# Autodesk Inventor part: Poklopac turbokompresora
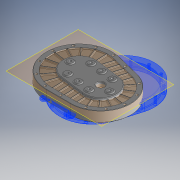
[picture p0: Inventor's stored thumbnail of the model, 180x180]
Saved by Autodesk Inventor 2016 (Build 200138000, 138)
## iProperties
Created: 2015-08
Part Number: Poklopac turbokompresora
Material: Generic
Document SubType Name: Modeling
Designer: stank
Density: 1 g/cm^3
Appearance: Default
Mass: 800.115 g
Surface Area: 1829.7 cm^2
Volume: 800.115 cm^3
Author: stank
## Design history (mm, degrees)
workplane "Work Plane3"
sketch "Sketch3"
  geometry: L1 (25.713, -105.228)-(-56.137, -104.923); L2 (26.085, -5.229)-(-52.114, 11.649); L3 (26.085, -5.229)-(-55.727, 5.076); L4 (25.769, -90.228)-(-56.081, -89.923); L5 (-32.512, 97.196)-(46.857, 77.194); L6 (50.522, 91.74)-(-28.846, 111.741); C1 r 9 at (26.085, -5.229) reference; C2 r 4.5 at (43.468, -93.366) reference; C3 r 4.5 at (-58.597, -126.199) reference; C4 r 4.5 at (-148.255, -75.856) reference; C5 r 4.5 at (-134.233, 101.873) reference; C6 r 4.5 at (-46.759, 125.523) reference; C7 r 4.5 at (25.538, 82.325) reference; A1 r 100 centre (26.085, -5.229) between (25.713, -105.228) and (50.522, 91.74); A2 r 110 centre (-55.727, 5.076) between (-28.846, 111.741) and (-56.137, -104.923); A3 r 85 centre (26.085, -5.229) between (25.769, -90.228) and (46.857, 77.194); A4 r 95 centre (-55.727, 5.076) between (-32.512, 97.196) and (-56.081, -89.923); 1 further point
  constraints: 12 end point, 8 point on circle, 6 tangent, 4 centre point, 2 parallel, 2 other
  dimensions: "d7" = 110 radius of A2; "d8" = 100 radius of A1; "d18" = 5 deg angle of L2 L3; "d26" = 15 distance between parallel lines of L1 L4; "d148" = 15 radial gap between concentric circles of A1 A3
extrude "Extrusion1" new body sketch "Sketch3" distance "d13" = 25; taper "d14" = 0 deg
sketch "Sketch7"
  geometry: L1 (50.522, 91.74)-(-28.846, 111.741) reference; L2 (-56.137, -104.923)-(25.713, -105.228) reference; C1 r 4 at (-41.402, 31.566) reference; C2 r 4 at (-38.197, -5.064) reference; C3 r 4 at (-13.762, -8.715) reference; C4 r 4 at (-4.556, 20.483) reference; C5 r 4 at (22.599, 34.619) reference; C6 r 4 at (51.797, 25.413) reference; C7 r 4 at (65.933, -1.742) reference; C8 r 4 at (56.727, -30.94) reference; C9 r 4 at (31.273, -44.891) reference; C10 r 4 at (0.374, -35.87) reference; A1 r 110 centre (-55.727, 5.076) between (-28.846, 111.741) and (-56.137, -104.923) reference; A2 r 100 centre (26.085, -5.229) between (25.713, -105.228) and (50.522, 91.74) reference; 1 further point
extrude "Extrusion3" join sketch "Sketch7" distance "d42" = 10; taper "d43" = 0 deg
sketch "Sketch8"
  geometry: L1 (25.769, -90.228)-(-56.081, -89.923) reference; L2 (-32.512, 97.196)-(46.857, 77.194) reference; C1 r 4 at (65.933, -1.742) reference; C2 r 4 at (56.727, -30.94) reference; C3 r 4 at (31.273, -44.891) reference; C4 r 4 at (0.374, -35.87) reference; C5 r 4 at (-13.762, -8.715) reference; C6 r 4 at (-38.197, -5.064) reference; C7 r 4 at (-4.556, 20.483) reference; C8 r 4 at (22.599, 34.619) reference; C9 r 4 at (51.797, 25.413) reference; C10 r 4 at (-41.402, 31.566) reference; C11 r 10 at (65.933, -1.742); C12 r 10 at (56.727, -30.94); C13 r 4 at (31.273, -44.891) reference; C14 r 10 at (31.273, -44.891); C15 r 10 at (0.374, -35.87); C16 r 4 at (-13.762, -8.715) reference; C17 r 10 at (-13.762, -8.715); C18 r 10 at (-38.197, -5.064); C19 r 10 at (-41.402, 31.566); C20 r 10 at (-4.556, 20.483); C21 r 4 at (22.599, 34.619) reference; C22 r 10 at (22.599, 34.619); C23 r 10 at (51.797, 25.413); A1 r 85 centre (26.085, -5.229) between (25.769, -90.228) and (46.857, 77.194) reference; A2 r 95 centre (-55.727, 5.076) between (-32.512, 97.196) and (-56.081, -89.923) reference; 1 further point
  constraints: 10 centre point, 10 coincident
  dimensions: "d44" = 20 diameter of C11; "d45" = 20 diameter of C12; "d46" = 20 diameter of C14; "d47" = 20 diameter of C15; "d48" = 20 diameter of C17; "d49" = 20 diameter of C20; "d50" = 20 diameter of C22; "d51" = 20 diameter of C23; "d52" = 20 diameter of C18; "d54" = 20 diameter of C19
extrude "Extrusion5" cut sketch "Sketch8" distance "d58" = 5; taper "d59" = 0 deg
sketch "Sketch10"
  geometry: C1 r 10 at (26.085, -5.229) reference; C2 r 11 at (26.085, -5.229); C3 r 16 at (26.085, -5.229); 1 further point
  constraints: 2 centre point, 2 coincident
  dimensions: "d60" = 1 radial gap between concentric circles of C1 C2; "d61" = 5 radial gap between concentric circles of C2 C3
extrude "Extrusion6" join sketch "Sketch10" distance "d62" = 3; taper "d63" = 0 deg
sketch "Sketch11"
  geometry: C1 r 11 at (0, 0) reference; 1 further point
extrude "Extrusion7" cut sketch "Sketch11" stored distance "d64" = 17; taper "d65" = 0 deg
chamfer "Chamfer3" distance "d71" = 1; stored, may be unused: second distance "d72" = 2, angle "d73" = 45 deg
workplane "Work Plane4"
sketch "Sketch12"
  geometry: L1 (26.085, -5.229)-(142.594, 145.734); L2 (26.085, -5.229)-(154.434, 22.85); L3 (26.085, -5.229)-(167.155, -24.202); L4 (26.085, -5.229)-(157.504, 77.979); L5 (101.371, 11.241)-(82.975, 7.217); L6 (89.461, -13.752)-(105.105, -15.856); L7 (75.965, 59.402)-(67.391, 48.291); L8 (92.041, 36.531)-(78.659, 28.059); L9 (-29.09, 110.772)-(50.278, 90.77) reference; L10 (25.717, -104.228)-(-56.133, -103.923) reference; L11 (-25.39, 100.364)-(51.872, 75.766) reference; L12 (30.981, -90.088)-(-49.967, -94.758) reference; L13 (-55.727, 5.076)-(-59.81, 104.993); L14 (-55.727, 5.076)-(-93.737, 97.571); L15 (-55.727, 5.076)-(-123.08, 78.992); L16 (-55.727, 5.076)-(-144.299, 51.499); L17 (-55.727, 5.076)-(-154.834, 18.406); L18 (-55.727, 5.076)-(-153.416, -16.295); L19 (-55.727, 5.076)-(26.085, -5.229); L20 (26.085, -5.229)-(51.872, 75.766); L21 (26.085, -5.229)-(51.872, 75.766); L22 (4.813, -2.549)-(31.782, 82.161); L23 (4.813, -2.549)-(8.443, -91.388); L24 (12.725, 88.229)-(-15.367, -0.007); L25 (-15.367, -0.007)-(-11.586, -92.543); L26 (-31.615, -93.699)-(-35.547, 2.534); L27 (-55.727, 5.076)-(-25.39, 100.364); L28 (-6.333, 94.296)-(-35.547, 2.534); L29 (49.768, 69.156)-(45.412, 55.475); L30 (49.768, 69.156)-(44.535, 52.72); L31 (29.678, 75.552)-(25.322, 61.871); L32 (9.933, 79.461)-(6.511, 68.711); L33 (-8.264, 88.229)-(-12.767, 74.086); L34 (-28.182, 91.595)-(-33.756, 74.086); L35 (-59.441, 95.979)-(-58.836, 81.156); L36 (-90.32, 89.255)-(-83.292, 72.154); L37 (-119.318, 74.864)-(-107.974, 62.414); L38 (-121.726, 39.668)-(-133.857, 46.026); L39 (-122.61, 14.072)-(-138.942, 16.268); L40 (-117.386, -8.413)-(-135.718, -12.423); L41 (-52.925, -63.49)-(-52.216, -80.841); L42 (-32.666, -67.96)-(-32.069, -82.577); L43 (-12.596, -67.814)-(-11.825, -86.696); L44 (7.37, -65.125)-(8.077, -82.428); L45 (26.085, -5.229)-(101.371, -44.688); L46 (26.085, -5.229)-(83.335, -68.057); L47 (26.085, -5.229)-(58.394, -83.849); L48 (26.085, -5.229)-(29.556, -90.158); L49 (-55.727, 5.076)-(-140.216, -48.418); L50 (-55.727, 5.076)-(-116.824, -74.089); L51 (-55.727, 5.076)-(-86.064, -90.211); L52 (-55.727, 5.076)-(-51.644, -94.84); L53 (83.335, -35.235)-(95.897, -41.818); L54 (65.44, -48.418)-(77.011, -61.116); L55 (49.052, -61.116)-(54.383, -74.089); L56 (28.634, -67.603)-(29.2, -81.44); L57 (-78.06, -65.073)-(-82.518, -79.075); L58 (-97.971, -49.661)-(-106.812, -61.116); L59 (-110.873, -29.84)-(-129.792, -41.818); C1 r 11 at (26.085, -5.229); C2 r 11 at (26.085, -5.229) reference; A1 r 100 centre (26.085, -5.229) between (25.713, -105.228) and (50.522, 91.74) reference; A2 r 110 centre (-55.727, 5.076) between (-28.846, 111.741) and (-56.137, -104.923) reference; A3 r 99 centre (26.085, -5.229) between (25.717, -104.228) and (50.278, 90.77) reference; A4 r 109 centre (-55.727, 5.076) between (-29.09, 110.772) and (-56.133, -103.923) reference; A5 r 85 centre (26.085, -5.229) between (30.981, -90.088) and (51.872, 75.766) reference; A6 r 100 centre (-55.727, 5.076) between (-25.39, 100.364) and (-49.967, -94.758) reference; A7 r 85 centre (26.085, -5.229) between (25.769, -90.228) and (46.857, 77.194) reference; A8 r 85 centre (26.085, -5.229) between (25.769, -90.228) and (46.857, 77.194) reference; 3 further points; 3 other entities
  constraints: 110 end point, 54 point on line, 14 point on circle, 6 parallel, 1 centre point, 1 coincident, 1 collinear, 1 perpendicular, 25 other
  dimensions: "d81" = 20 deg angle of L1 L4; "d82" = 20 deg angle of L2 L4; "d83" = 20 deg angle of L2 L3; "d194" = 20 deg angle of L13 L27; "d195" = 20 deg angle of L14 L13; "d196" = 20 deg angle of L14 L15; "d199" = 20 deg angle of L17 L16; "d200" = 20 deg angle of L17 L18; "d206" = 20 deg angle of L20 L1; "d207" = 20 deg angle of L15 L16; "d208" = 20 deg angle of L45 L3; "d209" = 20 deg angle of L46 L45; "d211" = 20 deg angle of L47 L46; "d212" = 20 deg angle of L48 L47; "d213" = 20 deg angle of L49 L18; "d214" = 20 deg angle of L50 L49; "d215" = 20 deg angle of L51 L50; "d216" = 20 deg angle of L51 L52; "d217" = 20 distance between parallel lines of L27 L28; "d218" = 20 distance between parallel lines of L24 L28; "d219" = 20 distance between parallel lines of L24 L22
  node "Projected Loop13"
sketch "Sketch13"
  geometry: L1 (26.085, -5.229)-(-31.513, 2.026); L2 (26.085, -5.229)-(-174.711, 20.063) reference; L3 (-55.727, 5.076)-(26.085, -5.229); L4 (-62.6, -49.493)-(19.212, -59.798); L5 (32.959, 49.34)-(-48.853, 59.645); A1 r 100 centre (-55.727, 5.076) between (-25.39, 100.364) and (-49.967, -94.758) reference; A2 r 55 centre (-55.727, 5.076) between (-48.853, 59.645) and (-62.6, -49.493); A3 r 55 centre (26.085, -5.229) between (19.212, -59.798) and (32.959, 49.34); 3 further points
  constraints: 12 end point, 4 point on circle, 4 tangent, 2 centre point, 2 collinear, 2 midpoint, 1 parallel
  dimensions: "d220" = 55 radius of A3
extrude "Extrusion8" join sketch "Sketch13" distance "d87" = 10; taper "d88" = 0 deg
fillet "Fillet9" dims "d99" = 1
fillet "Fillet10" dims "d100" = 2
chamfer "Chamfer4" distance "d138" = 1; stored, may be unused: second distance "d139" = 2, angle "d140" = 45 deg
fillet "Fillet12" dims "d150" = 2
sketch "Sketch18"
  geometry: C1 r 4 at (137.394, 67.018) reference; C2 r 4 at (95.482, 99.553) reference; C3 r 4 at (42.917, 106.773) reference; C4 r 4 at (-9.005, 94.468) reference; C5 r 4 at (-82.286, 68.869) reference; C6 r 4 at (-111.806, 30.842) reference; C7 r 4 at (-118.356, -16.851) reference; C8 r 4 at (-100.183, -61.429) reference; C9 r 4 at (-62.156, -90.949) reference; C10 r 4 at (15.184, -97.576) reference; C11 r 4 at (68.536, -96.62) reference; C12 r 4 at (150.203, -34.679) reference; C13 r 4 at (117.668, -76.591) reference; C14 r 4 at (157.423, 17.886) reference; C15 r 4 at (137.394, 67.018) reference; C16 r 4 at (95.482, 99.553) reference; C17 r 4 at (42.917, 106.773) reference; C18 r 4 at (-9.005, 94.468) reference; C19 r 4 at (-81.984, 68.471) reference; C20 r 4 at (-111.345, 30.648) reference; C21 r 4 at (-117.86, -16.788) reference; C22 r 4 at (-99.785, -61.127) reference
hole "Hole1" sketch "Sketch18" at (15.184, -97.576), (-62.156, -90.949), (-100.183, -61.429), (-118.356, -16.851), (-111.345, 30.648), (-81.984, 68.471), (-9.005, 94.468), (42.917, 106.773), (95.482, 99.553), (137.394, 67.018), (157.423, 17.886), (150.203, -34.679)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 diameter "d155" = 8; stored, may be unused: countersink angle "d159" = 90 deg, drill point angle "d161" = 118 deg; dims "d156" = 6, "d157" = 4, "d158" = 2, "d160" = 8
chamfer "Chamfer6" distance "d162" = 2; stored, may be unused: second distance "d163" = 2, angle "d164" = 45 deg
sketch "Sketch19"
  geometry: C1 r 11 at (26.085, -5.229) reference; C2 r 12 at (26.085, -5.229); 1 further point
  constraints: 1 centre point, 1 coincident
  dimensions: "d166" = 1 radial gap between concentric circles of C2 C1
extrude "Extrusion11" cut sketch "Sketch19" stored distance "d167" = 10; taper "d168" = 0 deg
workplane "Work Plane7"
sketch "Sketch21"
  geometry: L1 (-60, -27.257)-(-60, 50.054) reference; L2 (-60, 13.886)-(-59, 13.886); L3 (-59, 13.886)-(-59, 14.886); L4 (-59, 14.886)-(-60, 14.886); L5 (-60, 14.886)-(-60, 13.886); L6 (-47, 23.386)-(-60, 23.386); L7 (-60, 23.386)-(-60, 27.386); L8 (-60, 27.386)-(-47, 27.386); L9 (-47, 27.386)-(-47, 23.386); L10 (-50.113, -0.114)-(-87.752, -0.114) reference; 1 further point
  constraints: 18 end point, 4 horizontal, 4 parallel, 2 perpendicular, 2 point on line
  dimensions: "d176" = 28 diameter of L2 L10; "d177" = 1 distance of L2.start L2.end; "d178" = 1 distance of L2.end L3.end; "d179" = 4 distance between parallel lines of L8 L6; "d180" = 47 diameter of L6 L10; "d181" = 13 distance of L6.start L6.end
revolve "Revolution1" sketch "Sketch21" stored, may be unused: angle "d182" = 90 deg
workplane "Work Plane8"
sketch "Sketch22"
  geometry: L1 (1, 15)-(0, 15); L2 (0, 15)-(0, 16); L3 (0, 16)-(1, 16); L4 (1, 16)-(1, 15); L5 (1, 23.5)-(-12, 23.5); L6 (-12, 23.5)-(-12, 26.5); L7 (-12, 26.5)-(1, 26.5); L8 (1, 26.5)-(1, 23.5); L9 (-0.6, 23.5)-(-11.4, 23.5) reference; L10 (0, 0)-(17.307, 0); 4 further points; 2 other entities
  constraints: 20 end point, 4 horizontal, 4 parallel, 2 perpendicular, 1 point on line, 5 other
  dimensions: "d183" = 1 distance of L3.end L1.start; "d184" = 1 distance of L1.start L1.end; "d185" = 30 diameter of L1 L10; "d186" = 47 diameter of L5 L10; "d187" = 13 distance between parallel lines of L8 L6; "d188" = 3 distance of L7.end L5.start
revolve "Revolution2" sketch "Sketch22" stored, may be unused: angle "d189" = 90 deg
feature "Rib7" dims "d227" = 5, "d228" = 1, "d229" = 0, "d230" = 0, "d231" = 1, "d232" = 1
feature "Rib8" dims "d233" = 5, "d234" = 1, "d235" = 0, "d236" = 0, "d237" = 1, "d238" = 1
feature "Rib9" dims "d239" = 5, "d240" = 1, "d241" = 0, "d242" = 0, "d243" = 1, "d244" = 1
feature "Rib10" dims "d245" = 5, "d246" = 1, "d247" = 0, "d248" = 0, "d249" = 1, "d250" = 1
fillet "Fillet15" dims "d251" = 2
fillet "Fillet16" dims "d252" = 0.5
sketch "Sketch23"
  geometry: L1 (19.462, -57.813)-(-62.35, -47.508) reference; L2 (-49.103, 57.661)-(32.709, 47.356) reference; L3 (26.085, -5.229)-(-55.727, 5.076); L4 (26.085, -5.229)-(-55.727, 5.076); L5 (30.459, 29.497)-(-51.353, 39.802); L6 (-60.101, -29.649)-(21.712, -39.954); C1 r 12 at (26.085, -5.229) reference; A1 r 53 centre (-55.727, 5.076) between (-49.103, 57.661) and (-62.35, -47.508) reference; A2 r 53 centre (26.085, -5.229) between (19.462, -57.813) and (32.709, 47.356) reference; A3 r 35 centre (26.085, -5.229) between (21.712, -39.954) and (30.459, 29.497); A4 r 35 centre (-55.727, 5.076) between (-51.353, 39.802) and (-60.101, -29.649); 10 further points
  constraints: 10 end point, 6 point on circle, 4 coincident, 4 tangent, 3 midpoint, 2 centre point, 2 equal length
  dimensions: "d253" = 35 radius of A3
hole "Hole3" sketch "Sketch23" at (60.811, -9.603), (-90.452, 9.45), (30.459, 29.497), (21.712, -39.954), (-60.101, -29.649), (-51.353, 39.802), (-10.447, 34.649), (-19.195, -34.802) diameter "d254" = 8; stored, may be unused: countersink angle "d258" = 90 deg, drill point angle "d260" = 118 deg; dims "d255" = 6, "d256" = 4, "d257" = 2, "d259" = 10
sketch "Sketch24"
  geometry: C1 r 4 at (-51.353, 39.802) reference; C2 r 4 at (-10.447, 34.649) reference; C3 r 4 at (30.459, 29.497) reference; C4 r 4 at (60.811, -9.603) reference; C5 r 4 at (21.712, -39.954) reference; C6 r 4 at (-19.195, -34.802) reference; C7 r 4 at (-60.101, -29.649) reference; C8 r 4 at (-90.452, 9.45) reference; C9 r 10 at (-51.353, 39.802); C10 r 10 at (-10.447, 34.649); C11 r 10 at (30.459, 29.497); C12 r 10 at (60.811, -9.603); C13 r 10 at (21.712, -39.954); C14 r 10 at (-19.195, -34.802); C15 r 10 at (-60.101, -29.649); C16 r 10 at (-90.452, 9.45); 1 further point
  constraints: 8 centre point, 8 coincident
  dimensions: "d261" = 20 diameter of C9; "d262" = 20 diameter of C10; "d263" = 20 diameter of C11; "d264" = 20 diameter of C12; "d265" = 20 diameter of C13; "d266" = 20 diameter of C14; "d267" = 20 diameter of C15; "d268" = 20 diameter of C16
extrude "Extrusion12" join sketch "Sketch24" distance "d269" = 3; taper "d270" = 0 deg
fillet "Fillet17" dims "d271" = 3
chamfer "Chamfer8" distance "d272" = 2; stored, may be unused: second distance "d273" = 2, angle "d274" = 45 deg
sketch "Sketch25"
  geometry: C1 r 4 at (-51.797, 25.413) reference; C2 r 4 at (-65.933, -1.742) reference; C3 r 4 at (-22.599, 34.619) reference; C4 r 4 at (4.556, 20.483) reference; C5 r 4 at (13.762, -8.715) reference; C6 r 4 at (-0.374, -35.87) reference; C7 r 4 at (-31.273, -44.891) reference; C8 r 4 at (-56.727, -30.94) reference; A1 r 4 centre (41.402, 31.566) between (37.652, 30.172) and (44.631, 33.926) reference; A2 r 4 centre (41.402, 31.566) between (40.48, 35.458) and (38.662, 34.481) reference; A3 r 4 centre (41.402, 31.566) between (38.662, 34.481) and (37.652, 30.172) reference; A4 r 4 centre (41.402, 31.566) between (44.631, 33.926) and (40.48, 35.458) reference; A5 r 4 centre (38.197, -5.064) between (40.13, -8.566) and (34.403, -3.797) reference; A6 r 4 centre (38.197, -5.064) between (34.403, -3.797) and (40.13, -8.566) reference; 1 further point
extrude "Extrusion13" join sketch "Sketch25" stored distance "d275" = 2.5; taper "d276" = 0 deg
fillet "Fillet18" dims "d277" = 2
chamfer "Chamfer9" distance "d278" = 1; stored, may be unused: second distance "d279" = 2, angle "d280" = 45 deg
body "Solid1"
node "Reference1"
node "Reference2"
node "Reference12"
node "Reference13"
node "Reference14"
node "Reference15"
node "Reference16"
node "Reference17"
node "Reference25"
node "Reference26"
node "Reference27"
node "Reference28"
node "Reference29"
node "Reference30"
node "Reference31"
node "Reference32"
node "Reference33"
node "Reference34"
node "Reference35"
node "Reference57"
node "Projected Loop14"
node "Reference58"
node "Reference59"
node "Reference60"
node "Reference61"
node "Reference62"
node "Reference63"
node "Reference64"
node "Reference65"
node "Reference66"
node "Reference67"
node "Reference68"
node "Reference69"
node "Reference70"
node "Reference71"
node "Reference72"
node "Reference73"
node "Reference74"
node "Reference75"
node "Reference76"
node "Reference77"
node "Reference78"
node "Reference79"
other parameters: "d89" = 4
